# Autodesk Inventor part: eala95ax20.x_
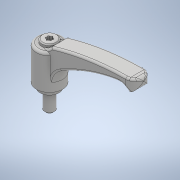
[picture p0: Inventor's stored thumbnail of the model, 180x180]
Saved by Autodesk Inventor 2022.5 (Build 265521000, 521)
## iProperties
Created: 2018-05
Part Number: eala95ax20.x_
Material: 一般
Document SubType Name: Modeling
Designer: imaocorp
Density: 1 g/cm^3
Appearance: 既定
Sending System: SOLIDWORKS 2016-2016286
MC: AMD64
MC_MODEL: AMD64 Family 21 Model 2 Stepping 0, AuthenticAMD
OS: Windows_NT
FRU: Parasolid Version 28.0, build 224,  7-29-2016
FORMAT: text
GUISE: transmit
KEY: eala95ax20
FILE: eala95ax20.x_t
DATE: Fri May 18 11:32:52 2018
Author: imaocorp
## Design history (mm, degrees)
feature "Base1"
node "ソリッド1"
